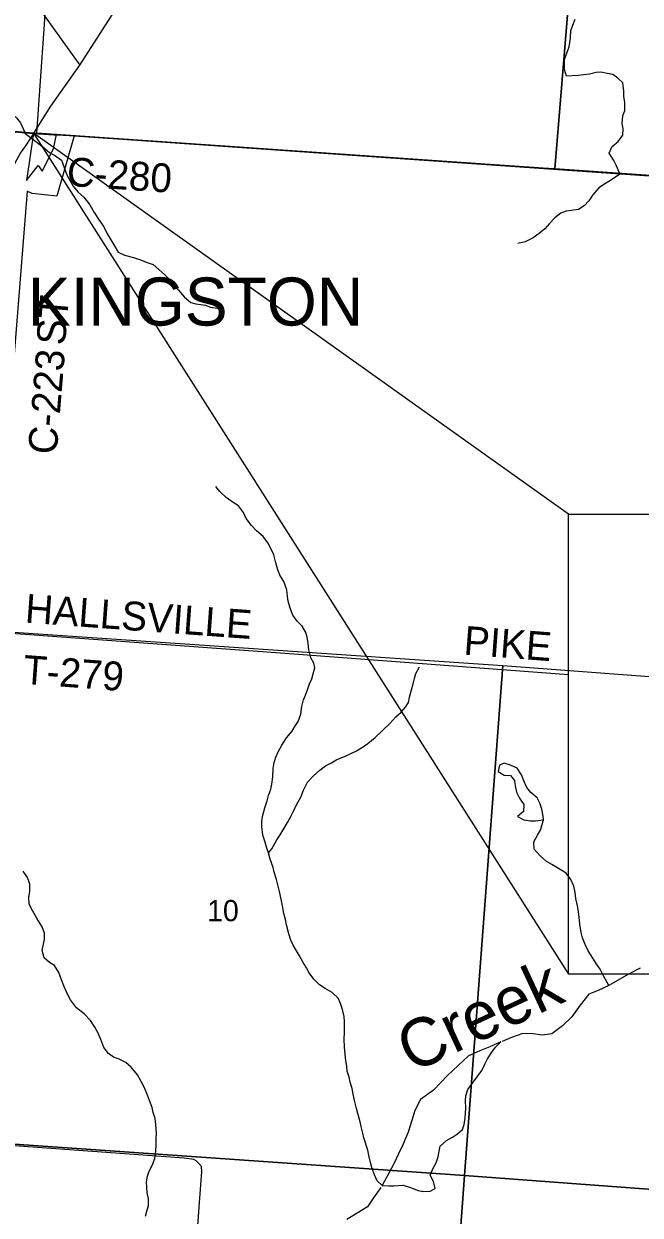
# Model space of a CAD drawing. Extents: x 0 to 42.5, y 0 to 22.
# Drawn here: x 3.672 to 4.279, y 14.84 to 16.014 of the extents above; entities that cross this region are included whole.
import ezdxf

# ---------------------------------------------------------------- set-up
doc = ezdxf.new("R2010")
doc.units = 0
for name, color, linetype in [('Default', 7, 'Continuous'), ('GM_X_Corporation', 7, 'Continuous'), ('GM_X_Corporation_Text', 7, 'Continuous'), ('GM_X_County_Road', 7, 'Continuous'), ('GM_X_County_Road_Text', 7, 'Continuous'), ('GM_X_Interchange_Ramps', 7, 'Continuous'), ('GM_X_Minor_Lake', 7, 'Continuous'), ('GM_X_Minor_River', 7, 'Continuous'), ('GM_X_Minor_River_Text', 7, 'Continuous'), ('GM_X_Section', 7, 'Continuous'), ('GM_X_Section_Text', 7, 'Continuous'), ('GM_X_State_Route', 7, 'Continuous'), ('GM_X_Township_Road', 7, 'Continuous'), ('GM_X_Township_Road_Text', 7, 'Continuous'), ('SH_Cut_Line', 7, 'Continuous'), ('SH_Text', 7, 'Continuous')]:
    doc.layers.add(name, color=color, linetype=linetype)

msp = doc.modelspace()

# ---------------------------------------------------------------- linework, layer by layer
at = {"layer": 'Default'}
msp.add_lwpolyline([(4.2087, 15.5307), (3.6812, 15.9061), (4.2087, 15.0772)], close=True, dxfattribs=at)
at = {"layer": 'GM_X_Corporation'}
msp.add_lwpolyline([(3.3788, 15.6459), (3.4506, 15.815), (3.458, 15.9202), (3.6354, 15.9103), (3.6812, 15.9061), (3.6743, 15.8595), (3.6855, 15.8744), (3.6897, 15.8689), (3.7008, 15.8907), (3.7036, 15.9048), (3.7213, 15.9037), (3.7042, 15.844), (3.6796, 15.8466), (3.6747, 15.8492), (3.654, 15.5891), (3.5841, 15.624), (3.5752, 15.6063), (3.532, 15.6278), (3.5207, 15.6163), (3.5089, 15.628), (3.4996, 15.6185), (3.4793, 15.6388)], close=True, dxfattribs=at)
at = {"layer": 'GM_X_County_Road'}
msp.add_line((3.6813, 15.9059), (3.7012, 15.9047), dxfattribs=at)
for points in [[(3.5444, 15.9144), (3.6355, 15.91), (3.6813, 15.9059)], [(3.7012, 15.9047), (3.7037, 15.9046), (3.7164, 15.9038)], [(3.7164, 15.9038), (3.7214, 15.9035), (4.4438, 15.8532)], [(3.8112, 14.3897), (3.8448, 14.8524), (3.8471, 14.8826), (3.8466, 14.8876), (3.8442, 14.8906), (3.8415, 14.8933), (3.8391, 14.8947), (3.8296, 14.8959), (3.5898, 14.9133), (3.641, 15.4146), (3.6544, 15.5918)]]:
    msp.add_lwpolyline(points, dxfattribs=at)
at = {"layer": 'GM_X_Interchange_Ramps'}
for points in [[(2.1, 19.059), (2.1, 16.0076), (2.5297, 15.9805), (3.1495, 15.9401), (3.4734, 15.9192), (3.5088, 15.917), (3.5443, 15.9147), (3.6354, 15.9103), (3.6812, 15.9061), (3.7036, 15.9048), (3.7213, 15.9037), (4.4437, 15.8535), (4.576, 15.8439), (4.7033, 15.8346), (4.834, 15.8246), (5.0466, 15.8101), (5.2142, 15.7986), (5.2389, 16.1139)], [(4.4437, 15.8535), (3.7213, 15.9037), (3.7036, 15.9048), (3.6812, 15.9061), (3.6354, 15.9103), (3.5443, 15.9147), (3.5088, 15.917), (3.4734, 15.9192), (3.1495, 15.9401), (2.5297, 15.9805), (2.1, 16.0076), (2.1, 14.1), (5.0849, 14.1)]]:
    msp.add_lwpolyline(points, dxfattribs=at)
at = {"layer": 'GM_X_Minor_Lake'}
for points in [[(4.1836, 15.2332), (4.1823, 15.2401), (4.1808, 15.2452), (4.1776, 15.2511), (4.1715, 15.2564), (4.1675, 15.2612), (4.1645, 15.2678), (4.1622, 15.2739), (4.1579, 15.2804), (4.1514, 15.2833), (4.1453, 15.2852), (4.1406, 15.2833), (4.1392, 15.2772), (4.1453, 15.2734), (4.1514, 15.273), (4.1554, 15.2681), (4.1561, 15.2631), (4.1572, 15.2567), (4.1603, 15.2509), (4.1644, 15.2445), (4.1641, 15.2378), (4.1583, 15.2327), (4.1646, 15.2295), (4.1711, 15.2285), (4.176, 15.2283)], [(4.176, 15.2283), (4.1838, 15.2295), (4.1836, 15.2332)]]:
    msp.add_lwpolyline(points, dxfattribs=at)
at = {"layer": 'GM_X_Minor_River'}
for points in [[(4.2591, 15.866), (4.2557, 15.8746), (4.2533, 15.8793), (4.2486, 15.8866), (4.2514, 15.8927), (4.2577, 15.8979), (4.262, 15.9042), (4.2626, 15.9104), (4.2615, 15.9162), (4.2622, 15.9232), (4.2641, 15.9285), (4.2641, 15.9367), (4.2632, 15.9424), (4.263, 15.9479), (4.262, 15.9557), (4.2573, 15.9605), (4.2522, 15.9642), (4.2467, 15.965), (4.2405, 15.9663), (4.2357, 15.9659), (4.2292, 15.9643), (4.218, 15.9629), (4.2066, 15.9623), (4.2046, 15.969), (4.2045, 15.9789), (4.2073, 15.9861), (4.2091, 15.9914), (4.2105, 15.9999), (4.211, 16.0075), (4.2129, 16.0128), (4.2151, 16.0187)], [(3.5457, 16.0089), (3.556, 15.9991), (3.5615, 15.9926), (3.564, 15.9863), (3.5678, 15.9794), (3.5724, 15.9723), (3.5769, 15.9661), (3.5836, 15.9558), (3.5892, 15.9485), (3.5928, 15.9437), (3.5994, 15.9377), (3.6056, 15.9367), (3.6121, 15.9366), (3.6187, 15.935), (3.6255, 15.9328), (3.6321, 15.9316), (3.6399, 15.9303), (3.6458, 15.9297), (3.6521, 15.929), (3.6585, 15.9265), (3.6643, 15.9213), (3.6684, 15.9163), (3.6728, 15.9062)], [(3.6725, 15.9063), (3.6904, 15.8928), (3.6967, 15.8873), (3.7016, 15.8846), (3.7088, 15.8797), (3.7113, 15.8723), (3.7139, 15.8651), (3.7173, 15.8593), (3.7202, 15.854), (3.7247, 15.8485), (3.7308, 15.8432), (3.7365, 15.8356), (3.7408, 15.828), (3.7459, 15.8205), (3.7503, 15.8139), (3.7535, 15.8076), (3.7563, 15.8027), (3.7603, 15.7962), (3.7647, 15.789), (3.7708, 15.7859), (3.7795, 15.7838), (3.7856, 15.7817), (3.7931, 15.7787), (3.799, 15.7767), (3.8045, 15.7718), (3.8104, 15.7667), (3.8153, 15.7621), (3.8189, 15.7568), (3.8241, 15.7516), (3.8301, 15.7446), (3.8362, 15.7392), (3.8411, 15.7379), (3.8459, 15.7375), (3.8506, 15.7366), (3.8555, 15.7347), (3.8624, 15.7339)], [(4.2593, 15.8659), (4.25, 15.8595), (4.2452, 15.8565), (4.2384, 15.8522), (4.2327, 15.8455), (4.2287, 15.8394), (4.2239, 15.8347), (4.2184, 15.8311), (4.2112, 15.83), (4.2064, 15.8294), (4.2011, 15.8273), (4.195, 15.8228), (4.1899, 15.8173), (4.1853, 15.8118), (4.1796, 15.8074), (4.1737, 15.8031), (4.1659, 15.7991), (4.1587, 15.7974)], [(3.9199, 15.4828), (3.918, 15.4906), (3.9152, 15.4969), (3.9121, 15.5024), (3.9074, 15.5087), (3.9009, 15.5144), (3.896, 15.5195), (3.8909, 15.5264), (3.8882, 15.5324), (3.8831, 15.5389), (3.8778, 15.5423), (3.871, 15.5471), (3.8647, 15.5532), (3.8608, 15.5581)], [(4.0247, 14.8691), (4.0199, 14.8737), (4.0172, 14.8796), (4.015, 14.8856), (4.0137, 14.8904), (4.0121, 14.8974), (4.0106, 14.9037), (4.0069, 14.9159), (4.0059, 14.9206), (4.0042, 14.9271), (4.0031, 14.9318), (4.001, 14.94), (3.9997, 14.945), (3.998, 14.9516), (3.9963, 14.9592), (3.9952, 14.9647), (3.9933, 14.971), (3.9923, 14.9757), (3.9904, 14.9818), (3.9899, 14.9868), (3.9889, 14.9923), (3.9884, 14.9984), (3.9876, 15.0058), (3.9875, 15.0128), (3.9877, 15.0206), (3.9877, 15.0305), (3.9875, 15.0356), (3.9858, 15.0424), (3.9837, 15.0483), (3.9813, 15.0537), (3.9756, 15.0594), (3.9687, 15.0632), (3.9629, 15.0668), (3.9574, 15.0725), (3.953, 15.0786), (3.9504, 15.0835), (3.9469, 15.0887), (3.9433, 15.0953), (3.9403, 15.1003), (3.9371, 15.106), (3.9348, 15.1109), (3.9329, 15.1172), (3.9305, 15.1261), (3.9294, 15.1311), (3.928, 15.137), (3.9265, 15.1446), (3.9254, 15.1512), (3.9237, 15.1588), (3.922, 15.1655), (3.9207, 15.1706), (3.9182, 15.1777), (3.9173, 15.1824), (3.9145, 15.1908), (3.9128, 15.1969), (3.9112, 15.2016), (3.909, 15.2083), (3.9073, 15.2142), (3.9062, 15.2227), (3.9062, 15.2278), (3.9067, 15.2328), (3.909, 15.2411), (3.9113, 15.2482), (3.9128, 15.2535), (3.9151, 15.2597), (3.9159, 15.2647), (3.9171, 15.2719), (3.9174, 15.2799), (3.9182, 15.286), (3.9201, 15.2911), (3.9222, 15.2964), (3.926, 15.303), (3.9306, 15.3101), (3.9357, 15.3165), (3.9388, 15.3214), (3.942, 15.3262), (3.9447, 15.3336), (3.9458, 15.341), (3.9474, 15.3477), (3.9491, 15.3524), (3.9516, 15.3585), (3.9533, 15.3636), (3.9554, 15.3685), (3.9569, 15.3733), (3.9584, 15.3792), (3.9575, 15.3839), (3.9545, 15.3891), (3.9526, 15.3969), (3.9518, 15.4033), (3.9509, 15.4094), (3.9496, 15.4141), (3.946, 15.4204), (3.9409, 15.4254), (3.9369, 15.4313), (3.934, 15.4379), (3.9323, 15.445), (3.9316, 15.4497), (3.9308, 15.456), (3.928, 15.4643), (3.924, 15.4706), (3.922, 15.4759), (3.9199, 15.4828)], [(3.9128, 15.1969), (3.916, 15.201), (3.9211, 15.2098), (3.9242, 15.2147), (3.9282, 15.2213), (3.9314, 15.2267), (3.9348, 15.2327), (3.9377, 15.2386), (3.9407, 15.2449), (3.9446, 15.2519), (3.9472, 15.2587), (3.9512, 15.2667), (3.9567, 15.2726), (3.9634, 15.2785), (3.9691, 15.2826), (3.9748, 15.2855), (3.9803, 15.2889), (3.9877, 15.2919), (3.9932, 15.2944), (3.9995, 15.2976), (4.0054, 15.3012), (4.0107, 15.3046), (4.018, 15.3105), (4.0252, 15.3175), (4.0324, 15.3243), (4.0383, 15.3308), (4.0436, 15.3355), (4.0478, 15.3404), (4.0507, 15.3452), (4.0518, 15.3503), (4.0537, 15.3577), (4.0553, 15.3634), (4.0566, 15.3687), (4.0581, 15.3735), (4.0616, 15.3801)], [(4.2484, 15.0661), (4.2433, 15.0749), (4.2398, 15.0821), (4.2365, 15.087), (4.2327, 15.0931), (4.228, 15.1002), (4.225, 15.1066), (4.2225, 15.1131), (4.2212, 15.1184), (4.2197, 15.1266), (4.219, 15.1336), (4.2184, 15.1389), (4.2173, 15.1446), (4.2159, 15.1519), (4.215, 15.1578), (4.2137, 15.1642), (4.211, 15.1707), (4.2063, 15.1768), (4.2004, 15.1806), (4.1923, 15.1853), (4.1869, 15.1884), (4.1807, 15.1939), (4.1746, 15.2004), (4.1744, 15.2076), (4.1779, 15.2144), (4.1809, 15.2192), (4.1838, 15.2295)], [(3.7914, 14.8389), (3.7927, 14.8437), (3.7944, 14.8494), (3.7943, 14.8562), (3.7931, 14.8619), (3.7928, 14.8674), (3.7926, 14.8726), (3.7935, 14.8781), (3.7951, 14.883), (3.7979, 14.8887), (3.8006, 14.8957), (3.8016, 14.9029), (3.8019, 14.9092), (3.8021, 14.9149), (3.8022, 14.9202), (3.8016, 14.9292), (3.8009, 14.935), (3.7992, 14.9411), (3.7982, 14.9459), (3.7954, 14.9527), (3.7935, 14.958), (3.7905, 14.9653), (3.7872, 14.9714), (3.7836, 14.9782), (3.7772, 14.9856), (3.7721, 14.9904), (3.7656, 14.9936), (3.7599, 14.9955), (3.755, 14.999), (3.7505, 15.0052), (3.7474, 15.0128), (3.7444, 15.0197), (3.7416, 15.0252), (3.7374, 15.0315), (3.7309, 15.0381), (3.7236, 15.0441), (3.7175, 15.0519), (3.7141, 15.0583), (3.7109, 15.0659), (3.7086, 15.0718), (3.706, 15.0789), (3.7016, 15.0857), (3.6969, 15.0887), (3.6915, 15.0935), (3.6897, 15.1007), (3.692, 15.1117), (3.692, 15.1178), (3.6895, 15.1239), (3.6848, 15.1319), (3.6804, 15.1393), (3.6768, 15.1464), (3.6764, 15.1532), (3.6776, 15.1589), (3.6774, 15.1661), (3.6752, 15.1726), (3.671, 15.1789)], [(4.2793, 15.0833), (4.2679, 15.0773), (4.2591, 15.0724), (4.2484, 15.0661), (4.2377, 15.0612), (4.2286, 15.0575), (4.2202, 15.0469), (4.2117, 15.0352), (4.2025, 15.0265), (4.1922, 15.0186), (4.1827, 15.0172), (4.1736, 15.0184), (4.1634, 15.0189), (4.1523, 15.0148), (4.1432, 15.0111)], [(4.0247, 14.8691), (4.0313, 14.8687), (4.0362, 14.8687), (4.041, 14.8691), (4.0457, 14.8693), (4.0527, 14.867), (4.0605, 14.8641), (4.0654, 14.8631), (4.0721, 14.8633), (4.077, 14.8662), (4.0753, 14.8728), (4.0721, 14.8793), (4.075, 14.8861), (4.078, 14.8914), (4.0801, 14.8973), (4.0809, 14.9028), (4.0822, 14.9078), (4.0883, 14.9133), (4.0942, 14.9167), (4.0992, 14.9199), (4.1039, 14.9241), (4.1056, 14.929), (4.1066, 14.9353), (4.107, 14.9404), (4.1072, 14.9451), (4.107, 14.9526), (4.1072, 14.9573), (4.1093, 14.9638), (4.1139, 14.97), (4.1184, 14.9761), (4.1232, 14.9825), (4.126, 14.9886), (4.1287, 14.9939), (4.1331, 15.0004), (4.1367, 15.0055), (4.142, 15.0107)], [(4.142, 15.0107), (4.131, 15.0058), (4.1211, 15.0017), (4.11, 14.9969), (4.0997, 14.9874), (4.0894, 14.9773), (4.0756, 14.9629), (4.0626, 14.9539), (4.0572, 14.9429), (4.0541, 14.9331), (4.0506, 14.9217), (4.0452, 14.9092), (4.0409, 14.9001), (4.0367, 14.891), (4.0313, 14.8812), (4.0247, 14.8691)], [(4.0234, 14.8672), (4.0163, 14.857), (4.0105, 14.8479), (3.9899, 14.8355)]]:
    msp.add_lwpolyline(points, dxfattribs=at)
at = {"layer": 'GM_X_Section'}
for points in [[(3.7198, 16.4108), (4.2367, 16.3778), (4.1951, 15.871), (4.1836, 15.8718), (3.6845, 15.9062)], [(4.2367, 16.3778), (4.7433, 16.3482), (4.705, 15.8357), (4.1951, 15.871)], [(3.6421, 15.4157), (4.1437, 15.3814), (4.1061, 14.8789), (3.5909, 14.9148), (3.6116, 15.1645)], [(4.1437, 15.3814), (4.6645, 15.3424), (4.6315, 14.8399), (4.1061, 14.8789)], [(3.5909, 14.9148), (4.1061, 14.8789), (4.0702, 14.3893), (3.5535, 14.425)], [(4.1061, 14.8789), (4.6315, 14.8399), (4.6015, 14.4962), (4.591, 14.3476), (4.0702, 14.3893)]]:
    msp.add_lwpolyline(points, close=True, dxfattribs=at)
at = {"layer": 'GM_X_State_Route'}
msp.add_line((3.6813, 15.9059), (3.6814, 15.9061), dxfattribs=at)
for points in [[(3.7269, 15.9734), (4.1214, 16.5882), (4.1404, 16.6173), (4.307, 16.8691), (4.3916, 16.9605), (4.5415, 17.1208), (4.6327, 17.2223), (4.6462, 17.237), (5.0398, 17.5223), (5.3632, 17.7531)], [(3.0863, 16.7502), (3.2586, 16.7395), (3.2705, 16.6979), (3.308, 16.5664), (3.3173, 16.5434), (3.7269, 15.9734)], [(3.6815, 15.9063), (3.698, 15.9328), (3.7269, 15.9734)], [(3.6353, 15.8229), (3.6375, 15.8273), (3.6539, 15.8588), (3.6595, 15.8706), (3.6623, 15.8757), (3.665, 15.8807), (3.6684, 15.8864), (3.6735, 15.8939), (3.6813, 15.9059)]]:
    msp.add_lwpolyline(points, dxfattribs=at)
at = {"layer": 'GM_X_Township_Road'}
msp.add_lwpolyline([(3.641, 15.4146), (3.9335, 15.3935), (4.2087, 15.3728)], dxfattribs=at)
at = {"layer": 'SH_Cut_Line'}
for points in [[(2.1, 20.9), (2.1, 16.0076), (2.5297, 15.9805), (3.1495, 15.9401), (3.4734, 15.9192), (3.5088, 15.917), (3.5443, 15.9147), (3.6354, 15.9103), (3.6812, 15.9061), (3.7036, 15.9048), (3.7213, 15.9037), (4.4437, 15.8535)], [(4.4437, 15.8535), (3.7213, 15.9037), (3.7036, 15.9048), (3.6812, 15.9061), (3.6354, 15.9103), (3.5443, 15.9147), (3.5088, 15.917), (3.4734, 15.9192), (3.1495, 15.9401), (2.5297, 15.9805), (2.1, 16.0076), (2.1, 14.1), (8.0699, 14.1)]]:
    msp.add_lwpolyline(points, dxfattribs=at)
at = {"layer": 'SH_Text'}
msp.add_lwpolyline([(4.2087, 15.5307), (5.9141, 15.5307), (5.9141, 15.0772), (4.2087, 15.0772)], close=True, dxfattribs=at)

# ---------------------------------------------------------------- texts
at = {"layer": 'GM_X_Corporation_Text'}
msp.add_text('KINGSTON', height=0.04735, rotation=0, dxfattribs=at).set_placement((3.6754, 15.7166))
at = {"layer": 'GM_X_County_Road_Text'}
for s, rotation, p in [('C-280', 356.1308, (3.7133, 15.8544)), ('ST', 85.2856, (3.7121, 15.6966)), ('C-223', 85.3395, (3.7038, 15.5889))]:
    msp.add_text(s, height=0.02841, rotation=rotation, dxfattribs=at).set_placement(p)
at = {"layer": 'GM_X_Minor_River_Text'}
msp.add_text('Creek', height=0.04735, rotation=25, dxfattribs=at).set_placement((4.054, 14.9794))
at = {"layer": 'GM_X_Section_Text'}
msp.add_text('10', height=0.02093, rotation=0, dxfattribs=at).set_placement((3.8523, 15.1295))
at = {"layer": 'GM_X_Township_Road_Text'}
for s, rotation, p in [('HALLSVILLE', 355.8344, (3.6721, 15.4239)), ('PIKE', 355.6723, (4.1046, 15.3923)), ('T-279', 355.7949, (3.6701, 15.3636))]:
    msp.add_text(s, height=0.02841, rotation=rotation, dxfattribs=at).set_placement(p)

doc.saveas('drawing.dxf')
